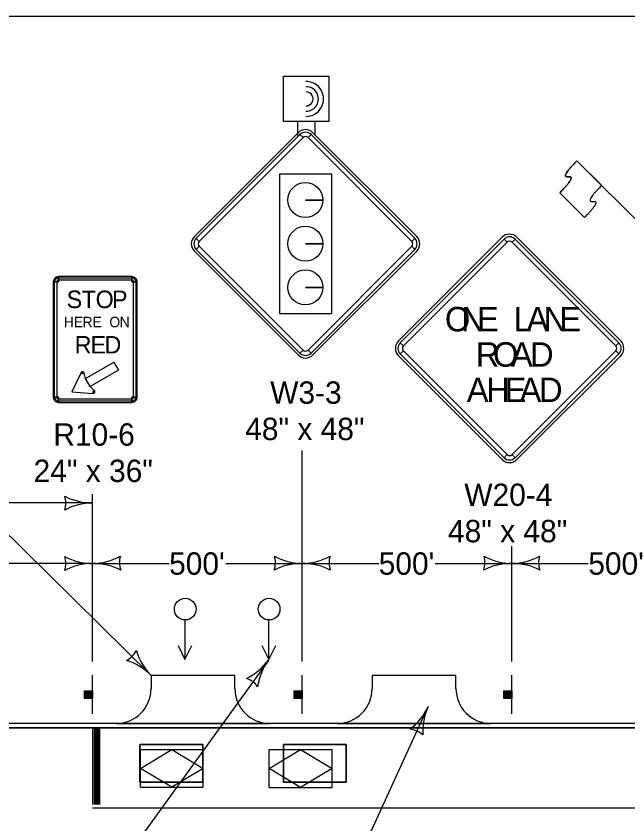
# Model space of a CAD drawing. Extents: x -2134934 to -2122394, y -2139046 to -2137036.
# Drawn here: x -2127867 to -2127429, y -2137614 to -2137036 of the extents above; entities that cross this region are included whole.
import ezdxf

# ---------------------------------------------------------------- set-up
doc = ezdxf.new("R2010")
doc.units = 0
for name, color, linetype in [('Barrier', 7, 'Continuous'), ('BridgeSuperStructureExisting', 7, 'Continuous'), ('Default', 7, 'Continuous'), ('DsnShtPlotIdentification', 7, 'Continuous'), ('DsnShtPlotShape', 7, 'Continuous'), ('dsnTextFinalPlan', 7, 'Continuous'), ('TC_Barrier', 7, 'Continuous')]:
    doc.layers.add(name, color=color, linetype=linetype)

msp = doc.modelspace()

# ---------------------------------------------------------------- linework, layer by layer
at = {"layer": 'Barrier'}
for p, q in [((-2127664.88, -2137119.33), (-2127739.13, -2137193.57)), ((-2127663.56, -2137120.65), (-2127661.35, -2137122.86)), ((-2127657.81, -2137122.86), (-2127655.6, -2137120.65)), ((-2127580.03, -2137193.57), (-2127654.28, -2137119.33)), ((-2127407.97, -2137196.68), (-2127465.31, -2137139.38)), ((-2127465.31, -2137139.38), (-2127447.62, -2137157.06)), ((-2127460, -2137180.05), (-2127477.68, -2137162.37)), ((-2127647.17, -2137167.55), (-2127659.67, -2137167.55)), ((-2127659.67, -2137167.55), (-2127647.17, -2137167.55)), ((-2127735.59, -2137197.11), (-2127737.8, -2137194.9)), ((-2127647.17, -2137198.8), (-2127659.67, -2137198.8)), ((-2127659.67, -2137198.8), (-2127647.17, -2137198.8)), ((-2127518.85, -2137194.14), (-2127593.09, -2137268.39)), ((-2127581.36, -2137194.9), (-2127583.56, -2137197.11)), ((-2127517.52, -2137195.47), (-2127515.31, -2137197.68)), ((-2127511.78, -2137197.68), (-2127509.57, -2137195.47)), ((-2127433.99, -2137268.39), (-2127508.24, -2137194.14)), ((-2127739.13, -2137204.18), (-2127664.88, -2137278.43)), ((-2127737.8, -2137202.85), (-2127735.59, -2137200.64)), ((-2127654.28, -2137278.43), (-2127580.03, -2137204.18)), ((-2127583.56, -2137200.64), (-2127581.36, -2137202.85)), ((-2127840.12, -2137226.09), (-2127836.37, -2137226.09)), ((-2127839.18, -2137226.09), (-2127837.62, -2137226.09)), ((-2127836.37, -2137226.09), (-2127836.37, -2137222.34)), ((-2127836.37, -2137224.84), (-2127836.37, -2137223.27)), ((-2127783.87, -2137222.34), (-2127783.87, -2137226.09)), ((-2127783.87, -2137223.27), (-2127783.87, -2137224.84)), ((-2127783.87, -2137226.09), (-2127780.12, -2137226.09)), ((-2127782.62, -2137226.09), (-2127781.06, -2137226.09)), ((-2127647.17, -2137230.05), (-2127659.67, -2137230.05)), ((-2127659.67, -2137230.05), (-2127647.17, -2137230.05)), ((-2127589.56, -2137271.93), (-2127591.77, -2137269.72)), ((-2127435.32, -2137269.72), (-2127437.53, -2137271.93)), ((-2127661.35, -2137274.89), (-2127663.56, -2137277.1)), ((-2127655.6, -2137277.1), (-2127657.81, -2137274.89)), ((-2127593.09, -2137279), (-2127518.85, -2137353.24)), ((-2127591.77, -2137277.67), (-2127589.56, -2137275.46)), ((-2127508.24, -2137353.24), (-2127433.99, -2137279)), ((-2127437.53, -2137275.46), (-2127435.32, -2137277.67)), ((-2127820.26, -2137291.07), (-2127819.15, -2137291.65)), ((-2127819.15, -2137291.65), (-2127817.93, -2137291.38)), ((-2127836.37, -2137308.59), (-2127840.12, -2137308.59)), ((-2127837.62, -2137308.59), (-2127839.18, -2137308.59)), ((-2127836.37, -2137312.34), (-2127836.37, -2137308.59)), ((-2127811.65, -2137304.64), (-2127811.7, -2137305.89)), ((-2127810.81, -2137303.72), (-2127811.65, -2137304.64)), ((-2127780.12, -2137308.59), (-2127783.87, -2137308.59)), ((-2127783.87, -2137308.59), (-2127783.87, -2137312.34)), ((-2127781.06, -2137308.59), (-2127782.62, -2137308.59)), ((-2127836.37, -2137311.4), (-2127836.37, -2137309.84)), ((-2127783.87, -2137309.84), (-2127783.87, -2137311.4)), ((-2127515.31, -2137349.71), (-2127517.52, -2137351.92)), ((-2127509.57, -2137351.92), (-2127511.78, -2137349.71))]:
    msp.add_line(p, q, dxfattribs=at)
for points in [[(-2127663.56, -2137120.65), (-2127737.8, -2137194.9), (-2127735.59, -2137197.11), (-2127661.35, -2137122.86), (-2127663.56, -2137120.65)], [(-2127581.36, -2137194.9), (-2127655.6, -2137120.65), (-2127657.81, -2137122.86), (-2127583.56, -2137197.11), (-2127581.36, -2137194.9)], [(-2127640.85, -2137148.93), (-2127678.31, -2137148.93), (-2127678.31, -2137248.82), (-2127640.85, -2137248.82), (-2127640.85, -2137148.93)], [(-2127517.52, -2137195.47), (-2127591.77, -2137269.72), (-2127589.56, -2137271.93), (-2127515.31, -2137197.68), (-2127517.52, -2137195.47)], [(-2127435.32, -2137269.72), (-2127509.57, -2137195.47), (-2127511.78, -2137197.68), (-2127437.53, -2137271.93), (-2127435.32, -2137269.72)], [(-2127737.8, -2137202.85), (-2127663.56, -2137277.1), (-2127661.35, -2137274.89), (-2127735.59, -2137200.64), (-2127737.8, -2137202.85)], [(-2127655.6, -2137277.1), (-2127581.36, -2137202.85), (-2127583.56, -2137200.64), (-2127657.81, -2137274.89), (-2127655.6, -2137277.1)], [(-2127836.37, -2137312.34), (-2127783.87, -2137312.34), (-2127783.87, -2137308.59), (-2127780.12, -2137308.59), (-2127780.12, -2137226.09), (-2127783.87, -2137226.09), (-2127783.87, -2137222.34), (-2127836.37, -2137222.34), (-2127836.37, -2137226.09), (-2127840.12, -2137226.09), (-2127840.12, -2137308.59), (-2127836.37, -2137308.59), (-2127836.37, -2137312.34)], [(-2127837.62, -2137226.09), (-2127837.62, -2137308.59), (-2127839.18, -2137308.59), (-2127839.18, -2137226.09), (-2127837.62, -2137226.09)], [(-2127783.87, -2137224.84), (-2127836.37, -2137224.84), (-2127836.37, -2137223.27), (-2127783.87, -2137223.27), (-2127783.87, -2137224.84)], [(-2127782.62, -2137308.59), (-2127782.62, -2137226.09), (-2127781.06, -2137226.09), (-2127781.06, -2137308.59), (-2127782.62, -2137308.59)], [(-2127591.77, -2137277.67), (-2127517.52, -2137351.92), (-2127515.31, -2137349.71), (-2127589.56, -2137275.46), (-2127591.77, -2137277.67)], [(-2127509.57, -2137351.92), (-2127435.32, -2137277.67), (-2127437.53, -2137275.46), (-2127511.78, -2137349.71), (-2127509.57, -2137351.92)], [(-2127796.75, -2137283.59), (-2127793.47, -2137289.27), (-2127813.77, -2137300.99), (-2127817.05, -2137295.31), (-2127796.75, -2137283.59)], [(-2127826.77, -2137304.71), (-2127811.7, -2137305.89), (-2127811.65, -2137304.64), (-2127810.81, -2137303.72), (-2127813.77, -2137300.99), (-2127817.05, -2137295.31), (-2127817.93, -2137291.38), (-2127819.15, -2137291.65), (-2127820.26, -2137291.07), (-2127826.77, -2137304.71)], [(-2127836.37, -2137309.84), (-2127783.87, -2137309.84), (-2127783.87, -2137311.4), (-2127836.37, -2137311.4), (-2127836.37, -2137309.84)]]:
    msp.add_lwpolyline(points, close=True, dxfattribs=at)
for centre in [(-2127659.67, -2137167.55), (-2127659.67, -2137198.8), (-2127659.67, -2137230.05)]:
    msp.add_circle(centre, 12.5, dxfattribs=at)
for centre, radius, start, end in [((-2127659.58, -2137124.63), 7.5, 44.99999, 134.99974), ((-2127659.58, -2137124.63), 5.62, 44.99999, 134.99974), ((-2127659.58, -2137124.63), 2.5, 44.99999, 134.99974), ((-2127513.54, -2137199.45), 7.5, 44.99999, 134.99974), ((-2127733.83, -2137198.88), 7.5, 134.99974, 224.99995), ((-2127733.83, -2137198.88), 5.62, 134.99974, 224.99995), ((-2127733.83, -2137198.88), 2.5, 134.99974, 224.99995), ((-2127585.33, -2137198.88), 2.5, 315.00016, 44.9998), ((-2127585.33, -2137198.88), 5.62, 315.00016, 44.9998), ((-2127585.33, -2137198.88), 7.5, 315.00016, 44.9998), ((-2127513.54, -2137199.45), 5.62, 44.99999, 134.99974), ((-2127513.54, -2137199.45), 2.5, 44.99999, 134.99974), ((-2127836.37, -2137226.09), 3.75, 90.00021, 179.99985), ((-2127836.37, -2137226.09), 2.81, 90.00021, 179.99985), ((-2127836.37, -2137226.09), 1.25, 90.00021, 179.99985), ((-2127783.87, -2137226.09), 3.75, 0, 90.00021), ((-2127783.87, -2137226.09), 2.81, 0, 90.00021), ((-2127783.87, -2137226.09), 1.25, 0, 90.00021), ((-2127587.79, -2137273.69), 7.5, 134.99974, 224.99995), ((-2127587.79, -2137273.69), 5.62, 134.99974, 224.99995), ((-2127587.79, -2137273.69), 2.5, 134.99974, 224.99995), ((-2127439.3, -2137273.69), 2.5, 315.00016, 44.9998), ((-2127439.3, -2137273.69), 5.62, 315.00016, 44.9998), ((-2127439.3, -2137273.69), 7.5, 315.00016, 44.9998), ((-2127659.58, -2137273.12), 7.5, 224.99995, 315.00016), ((-2127659.58, -2137273.12), 5.62, 224.99995, 315.00016), ((-2127659.58, -2137273.12), 2.5, 224.99995, 315.00016), ((-2127819.15, -2137291.65), 1.25, 12.62232, 152.27557), ((-2127836.37, -2137308.59), 3.75, 179.99985, 270.00006), ((-2127836.37, -2137308.59), 2.81, 179.99985, 270.00006), ((-2127836.37, -2137308.59), 1.25, 179.99985, 270.00006), ((-2127811.65, -2137304.64), 1.25, 267.72427, 47.37758), ((-2127783.87, -2137308.59), 3.75, 270.00006, 0.00027), ((-2127783.87, -2137308.59), 2.81, 270.00006, 0.00027), ((-2127783.87, -2137308.59), 1.25, 270.00006, 0.00027), ((-2127513.54, -2137347.94), 7.5, 224.99995, 315.00016), ((-2127513.54, -2137347.94), 5.62, 224.99995, 315.00016), ((-2127513.54, -2137347.94), 2.5, 224.99995, 315.00016)]:
    msp.add_arc(centre, radius, start, end, dxfattribs=at)
for points in [[(-2127477.68, -2137162.37), (-2127465.31, -2137149.99), (-2127477.68, -2137151.77), (-2127465.31, -2137139.38)], [(-2127447.62, -2137157.06), (-2127460, -2137169.44), (-2127447.63, -2137167.67), (-2127460, -2137180.05)]]:
    msp.add_open_spline(points, degree=2, dxfattribs=at)
at = {"layer": 'BridgeSuperStructureExisting'}
for p, q in [((-2127665.42, -2137111.41), (-2127665.42, -2137121.41)), ((-2127652.92, -2137111.41), (-2127652.92, -2137121.41)), ((-2127958.27, -2137322.38), (-2127770.13, -2137507.67)), ((-2127661.96, -2137497.66), (-2127661.96, -2137346.75)), ((-2127811.95, -2137497.66), (-2127811.95, -2137377.91)), ((-2127811.95, -2137384.33), (-2128113.68, -2137384.33)), ((-2127511.96, -2137497.66), (-2127511.96, -2137415.16)), ((-2127811.93, -2137427.66), (-2127893.7, -2137427.66)), ((-2127811.95, -2137427.66), (-2127757.21, -2137427.66)), ((-2127716.71, -2137427.66), (-2127661.96, -2137427.66)), ((-2127661.96, -2137427.66), (-2127607.21, -2137427.66)), ((-2127566.71, -2137427.66), (-2127511.96, -2137427.66)), ((-2127511.96, -2137427.66), (-2127457.21, -2137427.66)), ((-2127746.04, -2137468.02), (-2127746.04, -2137495.97)), ((-2127686.04, -2137468.02), (-2127686.04, -2137495.97)), ((-2127686.42, -2137497.23), (-2127838.98, -2137708.29)), ((-2127811.95, -2137535.16), (-2127811.95, -2137507.66)), ((-2127661.96, -2137535.16), (-2127661.96, -2137507.66)), ((-2127511.96, -2137535.16), (-2127511.96, -2137507.66)), ((-2127817.28, -2137524.3), (-2127817.28, -2137518.71)), ((-2127816.96, -2137518.71), (-2127816.96, -2137524.3)), ((-2127816.74, -2137524.3), (-2127816.74, -2137518.71)), ((-2127816.42, -2137518.71), (-2127816.42, -2137524.3)), ((-2127816.19, -2137524.3), (-2127816.21, -2137518.71)), ((-2127815.78, -2137518.71), (-2127815.76, -2137524.3)), ((-2127815.56, -2137524.3), (-2127815.56, -2137518.71)), ((-2127815.12, -2137518.71), (-2127815.12, -2137524.3)), ((-2127814.75, -2137524.3), (-2127814.75, -2137518.71)), ((-2127814.43, -2137518.71), (-2127814.41, -2137524.3)), ((-2127814.21, -2137524.3), (-2127814.21, -2137518.71)), ((-2127813.94, -2137518.71), (-2127813.94, -2137524.3)), ((-2127813.61, -2137524.3), (-2127813.61, -2137518.71)), ((-2127813.4, -2137518.71), (-2127813.4, -2137524.3)), ((-2127813.17, -2137524.3), (-2127813.17, -2137518.71)), ((-2127812.91, -2137518.71), (-2127812.91, -2137524.3)), ((-2127812.65, -2137524.3), (-2127812.65, -2137518.71)), ((-2127812.37, -2137518.71), (-2127812.37, -2137524.3)), ((-2127667.28, -2137524.3), (-2127667.28, -2137518.71)), ((-2127666.96, -2137518.71), (-2127666.96, -2137524.3)), ((-2127666.74, -2137524.3), (-2127666.74, -2137518.71)), ((-2127666.42, -2137518.71), (-2127666.42, -2137524.3)), ((-2127666.19, -2137524.3), (-2127666.21, -2137518.71)), ((-2127665.78, -2137518.71), (-2127665.76, -2137524.3)), ((-2127665.56, -2137524.3), (-2127665.56, -2137518.71)), ((-2127665.13, -2137518.71), (-2127665.13, -2137524.3)), ((-2127664.75, -2137524.3), (-2127664.75, -2137518.71)), ((-2127664.43, -2137518.71), (-2127664.41, -2137524.3)), ((-2127664.21, -2137524.3), (-2127664.21, -2137518.71)), ((-2127663.94, -2137518.71), (-2127663.94, -2137524.3)), ((-2127663.61, -2137524.3), (-2127663.61, -2137518.71)), ((-2127663.4, -2137518.71), (-2127663.4, -2137524.3)), ((-2127663.18, -2137524.3), (-2127663.18, -2137518.71)), ((-2127662.91, -2137518.71), (-2127662.91, -2137524.3)), ((-2127662.65, -2137524.3), (-2127662.65, -2137518.71)), ((-2127662.37, -2137518.71), (-2127662.37, -2137524.3)), ((-2127517.28, -2137524.3), (-2127517.28, -2137518.71)), ((-2127516.96, -2137518.71), (-2127516.96, -2137524.3)), ((-2127516.74, -2137524.3), (-2127516.74, -2137518.71)), ((-2127516.42, -2137518.71), (-2127516.42, -2137524.3)), ((-2127516.19, -2137524.3), (-2127516.21, -2137518.71)), ((-2127515.78, -2137518.71), (-2127515.76, -2137524.3)), ((-2127515.56, -2137524.3), (-2127515.56, -2137518.71)), ((-2127515.13, -2137518.71), (-2127515.13, -2137524.3)), ((-2127514.75, -2137524.3), (-2127514.75, -2137518.71)), ((-2127514.43, -2137518.71), (-2127514.41, -2137524.3)), ((-2127514.21, -2137524.3), (-2127514.21, -2137518.71)), ((-2127513.94, -2137518.71), (-2127513.94, -2137524.3)), ((-2127513.61, -2137524.3), (-2127513.61, -2137518.71)), ((-2127513.4, -2137518.71), (-2127513.4, -2137524.3)), ((-2127513.18, -2137524.3), (-2127513.18, -2137518.71)), ((-2127512.91, -2137518.71), (-2127512.91, -2137524.3)), ((-2127512.65, -2137524.3), (-2127512.65, -2137518.71)), ((-2127512.37, -2137518.71), (-2127512.37, -2137524.3)), ((-2127804.12, -2138038.74), (-2127571.87, -2137530.07)), ((-2127160.12, -2137545.16), (-2128660.12, -2137545.16)), ((-2127811.95, -2137545.16), (-2127811.95, -2137600.16)), ((-2127810.95, -2137545.16), (-2127810.95, -2137600.16)), ((-2127809.95, -2137545.16), (-2127809.95, -2137600.16)), ((-2127808.95, -2137545.16), (-2127808.95, -2137600.16)), ((-2127807.95, -2137545.16), (-2127807.95, -2137600.16)), ((-2127806.95, -2137545.16), (-2127806.95, -2137600.16)), ((-2127795.13, -2137542.16), (-2127685.13, -2137542.16)), ((-2127636.92, -2137542.16), (-2127526.92, -2137542.16)), ((-2127778.12, -2137557.19), (-2127733.12, -2137557.19)), ((-2127778.12, -2137584.19), (-2127778.12, -2137557.19)), ((-2127733.12, -2137557.19), (-2127778.12, -2137557.19)), ((-2127778.12, -2137557.19), (-2127778.12, -2137584.19)), ((-2127777.79, -2137587.78), (-2127777.79, -2137560.78)), ((-2127777.79, -2137560.78), (-2127732.79, -2137560.78)), ((-2127733.12, -2137557.19), (-2127733.12, -2137584.19)), ((-2127733.12, -2137584.19), (-2127733.12, -2137557.19)), ((-2127732.79, -2137587.78), (-2127732.79, -2137560.78)), ((-2127685.6, -2137587.86), (-2127685.6, -2137560.86)), ((-2127685.6, -2137560.86), (-2127640.6, -2137560.86)), ((-2127675.45, -2137557.19), (-2127630.45, -2137557.19)), ((-2127675.45, -2137584.19), (-2127675.45, -2137557.19)), ((-2127630.45, -2137557.19), (-2127675.45, -2137557.19)), ((-2127675.45, -2137557.19), (-2127675.45, -2137584.19)), ((-2127640.6, -2137587.86), (-2127640.6, -2137560.86)), ((-2127630.45, -2137557.19), (-2127630.45, -2137584.19)), ((-2127630.45, -2137584.19), (-2127630.45, -2137557.19)), ((-2127733.12, -2137584.19), (-2127778.12, -2137584.19)), ((-2127778.12, -2137584.19), (-2127733.12, -2137584.19)), ((-2127630.45, -2137584.19), (-2127675.45, -2137584.19)), ((-2127675.45, -2137584.19), (-2127630.45, -2137584.19)), ((-2127777.79, -2137587.78), (-2127732.79, -2137587.78)), ((-2127685.6, -2137587.86), (-2127640.6, -2137587.86))]:
    msp.add_line(p, q, dxfattribs=at)
for points in [[(-2127675.42, -2137111.41), (-2127675.42, -2137078.91), (-2127642.92, -2137078.91), (-2127642.92, -2137111.41)], [(-2127812.05, -2137518.71), (-2127812.05, -2137524.34), (-2127817.67, -2137524.34), (-2127817.67, -2137518.71)], [(-2127662.05, -2137518.71), (-2127662.05, -2137524.34), (-2127667.68, -2137524.34), (-2127667.68, -2137518.71)], [(-2127512.05, -2137518.71), (-2127512.05, -2137524.34), (-2127517.68, -2137524.34), (-2127517.68, -2137518.71)]]:
    msp.add_lwpolyline(points, close=True, dxfattribs=at)
for points in [[(-2127750.85, -2137486.34), (-2127745.85, -2137496.34), (-2127740.85, -2137486.34)], [(-2127690.85, -2137486.34), (-2127685.85, -2137496.34), (-2127680.85, -2137486.34)], [(-2127710.13, -2137517.16), (-2127710.13, -2137507.67), (-2127770.13, -2137507.67), (-2127770.13, -2137517.16)], [(-2127551.92, -2137517.16), (-2127551.92, -2137507.67), (-2127611.92, -2137507.67), (-2127611.92, -2137517.16)]]:
    msp.add_lwpolyline(points, dxfattribs=at)
for centre in [(-2127745.67, -2137460.29), (-2127685.67, -2137460.29)]:
    msp.add_circle(centre, 7.74, dxfattribs=at)
for centre, radius, start, end in [((-2127659.16, -2137095.18), 12.5, 269.40414, 90.54446), ((-2127659.16, -2137095.18), 12.5, 269.40414, 90.54446), ((-2127659.16, -2137095.18), 8.75, 269.40414, 90.54446), ((-2127659.16, -2137095.18), 5, 269.40414, 90.54446), ((-2127847.57, -2137427.66), 16.42, 342.26665, 17.73335), ((-2127811.93, -2137385.16), 42.5, 241.92751, 270), ((-2127812.71, -2137385.17), 42.5, 271.0176, 299.07249), ((-2127776.34, -2137427.04), 16.42, 163.26665, 198.73335), ((-2127697.57, -2137427.04), 16.42, 341.26665, 16.73335), ((-2127661.2, -2137385.17), 42.5, 240.92751, 268.9824), ((-2127662.71, -2137385.17), 42.5, 271.0176, 299.07249), ((-2127626.34, -2137427.04), 16.42, 163.26665, 198.73335), ((-2127547.57, -2137427.04), 16.42, 341.26665, 16.73335), ((-2127511.2, -2137385.17), 42.5, 240.92751, 268.9824), ((-2127512.71, -2137385.17), 42.5, 271.0176, 299.07249), ((-2127476.34, -2137427.04), 16.42, 163.26665, 198.73335), ((-2127811.93, -2137470.16), 42.5, 90, 118.07249), ((-2127811.23, -2137470.15), 42.5, 62.92751, 90.9824), ((-2127662.68, -2137470.15), 42.5, 89.0176, 117.07249), ((-2127661.23, -2137470.15), 42.5, 62.92751, 90.9824), ((-2127512.68, -2137470.15), 42.5, 89.0176, 117.07249), ((-2127511.23, -2137470.15), 42.5, 62.92751, 90.9824), ((-2127795.13, -2137517.16), 25, 270, 0), ((-2127685.13, -2137517.16), 25, 180, 270), ((-2127636.92, -2137517.16), 25, 270, 0), ((-2127526.92, -2137517.16), 25, 180, 270)]:
    msp.add_arc(centre, radius, start, end, dxfattribs=at)
at = {"layer": 'Default'}
msp.add_lwpolyline([(-2130231.95, -2137035.95), (-2127096.96, -2137035.95), (-2127096.96, -2139045.94), (-2130231.95, -2139045.94)], close=True, dxfattribs=at)
at = {"layer": 'DsnShtPlotIdentification'}
for p, q in [((-2127160.12, -2137542.16), (-2128660.12, -2137542.16)), ((-2127160.12, -2137542.16), (-2128660.12, -2137542.16)), ((-2127160.12, -2137545.16), (-2128660.12, -2137545.16)), ((-2128660.12, -2137545.16), (-2127810.12, -2137545.16)), ((-2127808.12, -2137545.16), (-2127807.12, -2137545.16)), ((-2127807.12, -2137545.16), (-2127806.12, -2137545.16)), ((-2127806.12, -2137545.16), (-2127805.12, -2137545.16)), ((-2127805.12, -2137545.16), (-2127160.12, -2137545.16)), ((-2127159.45, -2137602.66), (-2127811.95, -2137602.66))]:
    msp.add_line(p, q, dxfattribs=at)
for points in [[(-2128471.26, -2137545.16), (-2127158.8, -2137545.16)], [(-2127810.12, -2137545.16), (-2127809.12, -2137545.16), (-2127808.12, -2137545.16)]]:
    msp.add_lwpolyline(points, dxfattribs=at)
at = {"layer": 'DsnShtPlotShape'}
for centre, radius, start, end in [((-2127847.59, -2137384.37), 16.42, 342.26665, 17.73335), ((-2127811.95, -2137341.87), 42.5, 241.92751, 270), ((-2127811.95, -2137426.87), 42.5, 90, 118.07249), ((-2127795.21, -2137482.35), 16.42, 296.997, 332.46371), ((-2127739.94, -2137477.76), 42.5, 196.65786, 224.73035), ((-2127800.33, -2137537.58), 42.5, 44.73035, 72.80284), ((-2127720.29, -2137471.55), 42.5, 295.62849, 323.70098), ((-2127651.79, -2137521.87), 42.5, 143.70098, 171.77347), ((-2127707.13, -2137525.43), 16.42, 35.96763, 71.43433), ((-2127610.53, -2137512.41), 42.5, 307.38642, 335.45891), ((-2127533.21, -2137547.72), 42.5, 155.45891, 183.5314), ((-2127586.67, -2137562.48), 16.42, 47.72555, 83.19226)]:
    msp.add_arc(centre, radius, start, end, dxfattribs=at)
at = {"layer": 'dsnTextFinalPlan'}
for points in [[(-2127777.79, -2137574.28), (-2127755.29, -2137560.78), (-2127732.79, -2137574.28), (-2127755.29, -2137587.78)], [(-2127685.6, -2137574.36), (-2127663.1, -2137560.86), (-2127640.6, -2137574.36), (-2127663.1, -2137587.86)]]:
    msp.add_lwpolyline(points, close=True, dxfattribs=at)
at = {"layer": 'TC_Barrier'}
msp.add_line((-2127477.68, -2137162.37), (-2127460, -2137180.05), dxfattribs=at)
for points in [[(-2127465.31, -2137139.38), (-2127477.68, -2137151.77), (-2127465.31, -2137149.99), (-2127477.68, -2137162.37)], [(-2127447.62, -2137157.06), (-2127460, -2137169.44), (-2127447.63, -2137167.67), (-2127460, -2137180.05)]]:
    msp.add_open_spline(points, degree=2, dxfattribs=at)

# ---------------------------------------------------------------- texts
at = {"layer": 'Barrier'}
for s, height, p in [('S', 12.5, (-2127830.57, -2137244.84)), ('T', 12.5, (-2127819.8, -2137244.84)), ('O', 12.5, (-2127809.82, -2137244.84)), ('P', 12.5, (-2127798.07, -2137244.84)), ('O', 17.5, (-2127559.83, -2137261.51)), ('N', 17.5, (-2127548.05, -2137261.51)), ('E', 17.5, (-2127536.83, -2137261.51)), ('L', 17.5, (-2127510.58, -2137261.51)), ('A', 17.5, (-2127501.38, -2137261.51)), ('N', 17.5, (-2127489.11, -2137261.51)), ('E', 17.5, (-2127477.88, -2137261.51)), ('H', 7.5, (-2127832.64, -2137258.59)), ('E', 7.5, (-2127825.49, -2137258.59)), ('R', 7.5, (-2127819.24, -2137258.59)), ('E', 7.5, (-2127812.09, -2137258.59)), ('O', 7.5, (-2127800.02, -2137258.59)), ('N', 7.5, (-2127792.63, -2137258.59)), ('R', 12.5, (-2127824.81, -2137277.34)), ('E', 12.5, (-2127813.48, -2137277.34)), ('D', 12.5, (-2127803.52, -2137277.34)), ('R', 17.5, (-2127537.72, -2137286.82)), ('O', 17.5, (-2127525.43, -2137286.82)), ('A', 17.5, (-2127512.59, -2137286.82)), ('D', 17.5, (-2127498.94, -2137286.82)), ('A', 17.5, (-2127544.16, -2137312.13)), ('H', 17.5, (-2127530.29, -2137312.13)), ('E', 17.5, (-2127517.08, -2137312.13)), ('A', 17.5, (-2127506.36, -2137312.13)), ('D', 17.5, (-2127492.5, -2137312.13)), ('W3-3', 16, (-2127684.87, -2137313.34)), ('48" x 48"', 16, (-2127702.75, -2137339.34)), ('R10-6', 16, (-2127840.05, -2137343.34)), ('24" x 36"', 16, (-2127854.19, -2137369.34)), ('W20-4', 16, (-2127545.91, -2137386.44)), ('48" x 48"', 16, (-2127557.61, -2137412.44))]:
    msp.add_text(s, height=height, dxfattribs=at).set_placement(p)
at = {"layer": 'BridgeSuperStructureExisting'}
for p in [(-2127757.21, -2137435.66), (-2127607.21, -2137435.66), (-2127457.21, -2137435.66)]:
    msp.add_text("500'", height=16, dxfattribs=at).set_placement(p)

doc.saveas('drawing.dxf')
